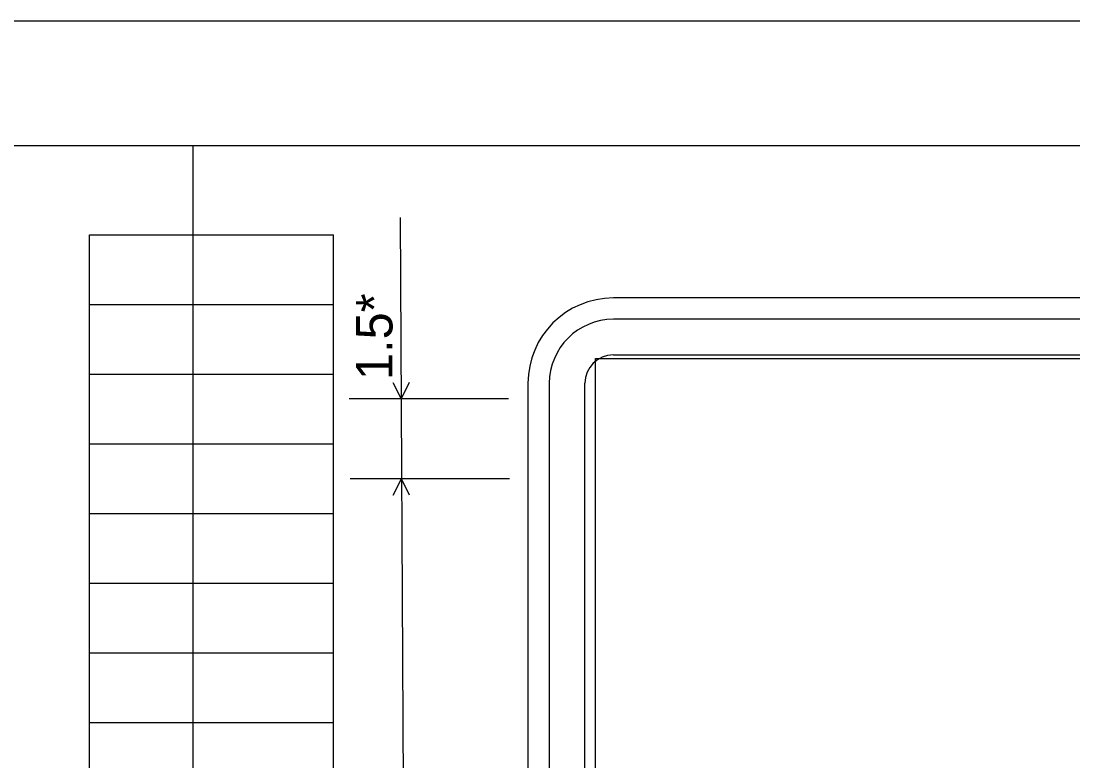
# Model space of a CAD drawing. Extents: x -39.4 to 36.9, y -12.9 to 28.
# Drawn here: x -7.307 to -3.081, y 6.119 to 9.093 of the extents above; entities that cross this region are included whole.
import ezdxf

# ---------------------------------------------------------------- set-up
doc = ezdxf.new("R2010")
doc.units = 0
for name, color, linetype in [('PM_P_Text', 7, 'Continuous'), ('SC_Scratch1', 7, 'Continuous'), ('SH_Border', 7, 'Continuous'), ('SH_Cut_Line', 7, 'Continuous'), ('SH_Data', 7, 'Continuous'), ('SH_Text', 7, 'Continuous')]:
    doc.layers.add(name, color=color, linetype=linetype)

msp = doc.modelspace()

# ---------------------------------------------------------------- linework, layer by layer
at = {"layer": 'PM_P_Text'}
for p, q in [((-5.7836, 8.3033), (-5.7522, 2.0743)), ((-5.8131, 7.6405), (-5.7804, 7.575)), ((-5.7477, 7.6405), (-5.7804, 7.575)), ((-5.8118, 7.1875), (-5.779, 7.2529)), ((-5.7463, 7.1875), (-5.779, 7.2529))]:
    msp.add_line(p, q, dxfattribs=at)
at = {"layer": 'SC_Scratch1'}
for p, q in [((-7.0313, -11.9269), (-7.0313, 8.2331)), ((-7.0313, 8.2331), (-6.0513, 8.2331)), ((-6.0513, -11.9269), (-6.0513, 8.2331)), ((-7.0313, 7.9531), (-6.0513, 7.9531)), ((-7.0313, 7.6731), (-6.0513, 7.6731)), ((-7.0313, 7.3931), (-6.0513, 7.3931)), ((-7.0313, 7.1131), (-6.0513, 7.1131)), ((-7.0313, 6.8331), (-6.0513, 6.8331)), ((-7.0313, 6.5531), (-6.0513, 6.5531)), ((-7.0313, 6.2731), (-6.0513, 6.2731))]:
    msp.add_line(p, q, dxfattribs=at)
at = {"layer": 'SH_Border'}
msp.add_lwpolyline([(-14.3713, 8.5931), (17.1287, 8.5931), (17.1287, -12.4069), (-14.3713, -12.4069)], close=True, dxfattribs=at)
at = {"layer": 'SH_Cut_Line'}
msp.add_lwpolyline([(-16.3713, -12.9069), (17.6287, -12.9069), (17.6287, 9.0931), (-16.3713, 9.0931)], close=True, dxfattribs=at)
at = {"layer": 'SH_Data'}
for p, q in [((-5.3484, 7.575), (-5.9885, 7.575)), ((-5.345, 7.2529), (-5.9851, 7.2529))]:
    msp.add_line(p, q, dxfattribs=at)
at = {"layer": 'SH_Text'}
for p, q in [((-6.6169, 8.5931), (-6.6169, -1.1935)), ((-1.4985, 7.9799), (-4.9275, 7.9799)), ((-4.9996, 2.7365), (-4.9996, 7.7369)), ((-4.9996, 7.7369), (-1.4263, 7.7369)), ((-5.2704, 7.637), (-5.2704, 2.8364))]:
    msp.add_line(p, q, dxfattribs=at)
for points in [[(-1.4985, 7.8942), (-4.9275, 7.8942)], [(-4.9275, 7.7513), (-1.4985, 7.7513)], [(-5.1847, 7.637), (-5.1847, 2.8364)], [(-5.0418, 2.8364), (-5.0418, 7.637)]]:
    msp.add_lwpolyline(points, dxfattribs=at)
for radius in [0.3429, 0.2572, 0.1143]:
    msp.add_arc((-4.9275, 7.637), radius, 90.0002, 179.9998, dxfattribs=at)

# ---------------------------------------------------------------- texts
at = {"layer": 'PM_P_Text'}
msp.add_text('1.5*', height=0.1463, rotation=90.0002, dxfattribs=at).set_placement((-5.8147, 7.6503))

doc.saveas('drawing.dxf')
